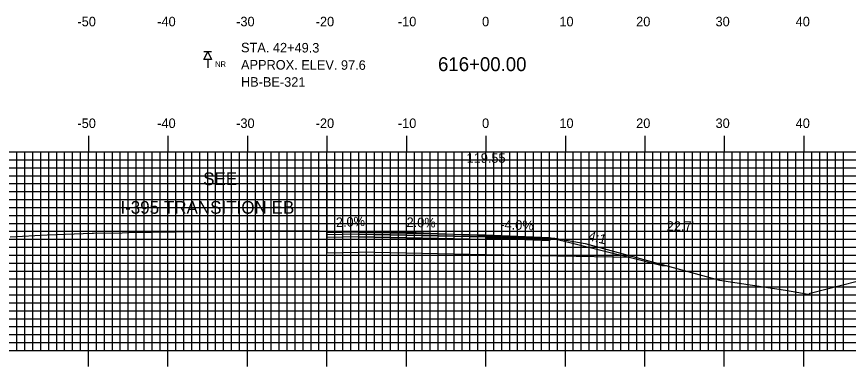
# Model space of a CAD drawing. Extents: x 844536 to 844879, y 363538 to 363758.
# Drawn here: x 844642.9 to 844747.6, y 363643.7 to 363687.7 of the extents above; entities that cross this region are included whole.
import ezdxf

# ---------------------------------------------------------------- set-up
doc = ezdxf.new("R2010")
doc.units = 0
for name, color, linetype in [('ANNOTATION', 7, 'Continuous'), ('BORING - NO REFUSAL', 7, 'Continuous'), ('D_Roadway_Centerline_Text', 7, 'Continuous'), ('D_Roadway_Edge_Shoulder', 7, 'Continuous'), ('D_Roadway_Edge_TW', 7, 'Continuous'), ('D_Roadway_FinishedGrade', 7, 'Continuous'), ('D_Roadway_Pavement', 7, 'Continuous'), ('D_Roadway_SlopeLines', 7, 'Continuous'), ('D_Roadway_SubGrade', 7, 'Continuous'), ('D_Text_Standard', 7, 'Continuous'), ('H_V ANNOTATION', 7, 'Continuous'), ('M_Roadway_Centerline', 7, 'Continuous'), ('MAJOR', 7, 'Continuous'), ('MINOR', 7, 'Continuous'), ('S_Roadway_Centerline', 7, 'Continuous')]:
    doc.layers.add(name, color=color, linetype=linetype)

msp = doc.modelspace()

# ---------------------------------------------------------------- linework, layer by layer
at = {"layer": 'BORING - NO REFUSAL'}
for p, q in [((844667.44, 363683.32), (844666.48, 363683.32)), ((844666.96, 363682.36), (844666.96, 363681.3))]:
    msp.add_line(p, q, dxfattribs=at)
msp.add_lwpolyline([(844666.96, 363683.32), (844667.44, 363682.36), (844666.48, 363682.36)], close=True, dxfattribs=at)
at = {"layer": 'D_Roadway_Edge_Shoulder'}
msp.add_lwpolyline([(844701.96, 363660.27), (844709.96, 363659.95), (844709.96, 363659.7), (844701.96, 363660.02)], close=True, dxfattribs=at)
at = {"layer": 'D_Roadway_Edge_TW'}
msp.add_lwpolyline([(844685.96, 363660.59), (844701.96, 363660.27), (844701.96, 363660.02), (844685.96, 363660.34)], close=True, dxfattribs=at)
at = {"layer": 'D_Roadway_FinishedGrade'}
for p, q in [((844685.96, 363660.59), (844681.96, 363660.51)), ((844685.96, 363660.34), (844681.96, 363660.26)), ((844685.96, 363660.01), (844681.96, 363659.93))]:
    msp.add_line(p, q, dxfattribs=at)
msp.add_lwpolyline([(844720.14, 363657.41), (844724.14, 363656.41), (844724.69, 363656.4)], dxfattribs=at)
at = {"layer": 'D_Roadway_Pavement'}
for points in [[(844685.96, 363660.34), (844701.96, 363660.02), (844701.96, 363659.69), (844685.96, 363660.01)], [(844701.96, 363660.02), (844709.96, 363659.7), (844709.96, 363659.53), (844701.96, 363659.85)]]:
    msp.add_lwpolyline(points, close=True, dxfattribs=at)
msp.add_lwpolyline([(844701.96, 363660.02), (844701.96, 363659.69)], dxfattribs=at)
msp.add_lwpolyline([(844701.96, 363660.02), (844701.96, 363659.69)], dxfattribs=at)
at = {"layer": 'D_Roadway_SlopeLines'}
msp.add_lwpolyline([(844709.96, 363659.95), (844710.39, 363659.84)], dxfattribs=at)
at = {"layer": 'D_Roadway_SubGrade'}
msp.add_line((844681.96, 363669.11), (844681.96, 363658.01), dxfattribs=at)
msp.add_lwpolyline([(844681.96, 363659.93), (844681.96, 363660.18), (844681.96, 363660.43), (844681.96, 363658.01), (844685.96, 363658.09), (844685.96, 363660.01)], dxfattribs=at)
for points in [[(844685.96, 363660.01), (844701.96, 363659.69), (844701.96, 363657.77), (844685.96, 363658.09)], [(844701.96, 363659.69), (844701.96, 363660.02), (844709.96, 363659.7), (844709.96, 363659.95), (844720.14, 363657.41), (844701.96, 363657.77)]]:
    msp.add_lwpolyline(points, close=True, dxfattribs=at)
at = {"layer": 'MAJOR'}
for p, q in [((844651.96, 363672.73), (844651.96, 363670.72)), ((844661.96, 363672.73), (844661.96, 363670.72)), ((844671.96, 363672.73), (844671.96, 363670.72)), ((844681.96, 363672.73), (844681.96, 363670.72)), ((844691.96, 363672.73), (844691.96, 363670.72)), ((844701.96, 363672.73), (844701.96, 363670.72)), ((844711.96, 363672.73), (844711.96, 363670.72)), ((844721.96, 363672.73), (844721.96, 363670.72)), ((844731.96, 363672.73), (844731.96, 363670.72)), ((844741.96, 363672.73), (844741.96, 363670.72)), ((844561.96, 363670.72), (844841.96, 363670.72)), ((844561.96, 363670.72), (844841.96, 363670.72)), ((844651.96, 363645.72), (844651.96, 363670.72)), ((844661.96, 363645.72), (844661.96, 363670.72)), ((844671.96, 363645.72), (844671.96, 363670.72)), ((844681.96, 363645.72), (844681.96, 363670.72)), ((844691.96, 363645.72), (844691.96, 363670.72)), ((844701.96, 363645.72), (844701.96, 363670.72)), ((844711.96, 363645.72), (844711.96, 363670.72)), ((844721.96, 363645.72), (844721.96, 363670.72)), ((844731.96, 363645.72), (844731.96, 363670.72)), ((844741.96, 363645.72), (844741.96, 363670.72)), ((844561.96, 363665.72), (844841.96, 363665.72)), ((844561.96, 363660.72), (844841.96, 363660.72)), ((844561.96, 363655.72), (844841.96, 363655.72)), ((844561.96, 363650.72), (844841.96, 363650.72)), ((844561.96, 363645.72), (844841.96, 363645.72)), ((844561.96, 363645.72), (844841.96, 363645.72)), ((844651.96, 363643.72), (844651.96, 363645.72)), ((844661.96, 363643.72), (844661.96, 363645.72)), ((844671.96, 363643.72), (844671.96, 363645.72)), ((844681.96, 363643.72), (844681.96, 363645.72)), ((844691.96, 363643.72), (844691.96, 363645.72)), ((844701.96, 363643.72), (844701.96, 363645.72)), ((844711.96, 363643.72), (844711.96, 363645.72)), ((844721.96, 363643.72), (844721.96, 363645.72)), ((844731.96, 363643.72), (844731.96, 363645.72)), ((844741.96, 363643.72), (844741.96, 363645.72))]:
    msp.add_line(p, q, dxfattribs=at)
at = {"layer": 'MINOR'}
for p, q in [((844642.96, 363645.72), (844642.96, 363670.72)), ((844643.96, 363645.72), (844643.96, 363670.72)), ((844644.96, 363645.72), (844644.96, 363670.72)), ((844645.96, 363645.72), (844645.96, 363670.72)), ((844646.96, 363645.72), (844646.96, 363670.72)), ((844647.96, 363645.72), (844647.96, 363670.72)), ((844648.96, 363645.72), (844648.96, 363670.72)), ((844649.96, 363645.72), (844649.96, 363670.72)), ((844650.96, 363645.72), (844650.96, 363670.72)), ((844652.96, 363645.72), (844652.96, 363670.72)), ((844653.96, 363645.72), (844653.96, 363670.72)), ((844654.96, 363645.72), (844654.96, 363670.72)), ((844655.96, 363645.72), (844655.96, 363670.72)), ((844656.96, 363645.72), (844656.96, 363670.72)), ((844657.96, 363645.72), (844657.96, 363670.72)), ((844658.96, 363645.72), (844658.96, 363670.72)), ((844659.96, 363645.72), (844659.96, 363670.72)), ((844660.96, 363645.72), (844660.96, 363670.72)), ((844662.96, 363645.72), (844662.96, 363670.72)), ((844663.96, 363645.72), (844663.96, 363670.72)), ((844664.96, 363645.72), (844664.96, 363670.72)), ((844665.96, 363645.72), (844665.96, 363670.72)), ((844666.96, 363645.72), (844666.96, 363670.72)), ((844667.96, 363645.72), (844667.96, 363670.72)), ((844668.96, 363645.72), (844668.96, 363670.72)), ((844669.96, 363645.72), (844669.96, 363670.72)), ((844670.96, 363645.72), (844670.96, 363670.72)), ((844672.96, 363645.72), (844672.96, 363670.72)), ((844673.96, 363645.72), (844673.96, 363670.72)), ((844674.96, 363645.72), (844674.96, 363670.72)), ((844675.96, 363645.72), (844675.96, 363670.72)), ((844676.96, 363645.72), (844676.96, 363670.72)), ((844677.96, 363645.72), (844677.96, 363670.72)), ((844678.96, 363645.72), (844678.96, 363670.72)), ((844679.96, 363645.72), (844679.96, 363670.72)), ((844680.96, 363645.72), (844680.96, 363670.72)), ((844682.96, 363645.72), (844682.96, 363670.72)), ((844683.96, 363645.72), (844683.96, 363670.72)), ((844684.96, 363645.72), (844684.96, 363670.72)), ((844685.96, 363645.72), (844685.96, 363670.72)), ((844686.96, 363645.72), (844686.96, 363670.72)), ((844687.96, 363645.72), (844687.96, 363670.72)), ((844688.96, 363645.72), (844688.96, 363670.72)), ((844689.96, 363645.72), (844689.96, 363670.72)), ((844690.96, 363645.72), (844690.96, 363670.72)), ((844692.96, 363645.72), (844692.96, 363670.72)), ((844693.96, 363645.72), (844693.96, 363670.72)), ((844694.96, 363645.72), (844694.96, 363670.72)), ((844695.96, 363645.72), (844695.96, 363670.72)), ((844696.96, 363645.72), (844696.96, 363670.72)), ((844697.96, 363645.72), (844697.96, 363670.72)), ((844698.96, 363645.72), (844698.96, 363670.72)), ((844699.96, 363645.72), (844699.96, 363670.72)), ((844700.96, 363645.72), (844700.96, 363670.72)), ((844702.96, 363645.72), (844702.96, 363670.72)), ((844703.96, 363645.72), (844703.96, 363670.72)), ((844704.96, 363645.72), (844704.96, 363670.72)), ((844705.96, 363645.72), (844705.96, 363670.72)), ((844706.96, 363645.72), (844706.96, 363670.72)), ((844707.96, 363645.72), (844707.96, 363670.72)), ((844708.96, 363645.72), (844708.96, 363670.72)), ((844709.96, 363645.72), (844709.96, 363670.72)), ((844710.96, 363645.72), (844710.96, 363670.72)), ((844712.96, 363645.72), (844712.96, 363670.72)), ((844713.96, 363645.72), (844713.96, 363670.72)), ((844714.96, 363645.72), (844714.96, 363670.72)), ((844715.96, 363645.72), (844715.96, 363670.72)), ((844716.96, 363645.72), (844716.96, 363670.72)), ((844717.96, 363645.72), (844717.96, 363670.72)), ((844718.96, 363645.72), (844718.96, 363670.72)), ((844719.96, 363645.72), (844719.96, 363670.72)), ((844720.96, 363645.72), (844720.96, 363670.72)), ((844722.96, 363645.72), (844722.96, 363670.72)), ((844723.96, 363645.72), (844723.96, 363670.72)), ((844724.96, 363645.72), (844724.96, 363670.72)), ((844725.96, 363645.72), (844725.96, 363670.72)), ((844726.96, 363645.72), (844726.96, 363670.72)), ((844727.96, 363645.72), (844727.96, 363670.72)), ((844728.96, 363645.72), (844728.96, 363670.72)), ((844729.96, 363645.72), (844729.96, 363670.72)), ((844730.96, 363645.72), (844730.96, 363670.72)), ((844732.96, 363645.72), (844732.96, 363670.72)), ((844733.96, 363645.72), (844733.96, 363670.72)), ((844734.96, 363645.72), (844734.96, 363670.72)), ((844735.96, 363645.72), (844735.96, 363670.72)), ((844736.96, 363645.72), (844736.96, 363670.72)), ((844737.96, 363645.72), (844737.96, 363670.72)), ((844738.96, 363645.72), (844738.96, 363670.72)), ((844739.96, 363645.72), (844739.96, 363670.72)), ((844740.96, 363645.72), (844740.96, 363670.72)), ((844742.96, 363645.72), (844742.96, 363670.72)), ((844743.96, 363645.72), (844743.96, 363670.72)), ((844744.96, 363645.72), (844744.96, 363670.72)), ((844745.96, 363645.72), (844745.96, 363670.72)), ((844746.96, 363645.72), (844746.96, 363670.72)), ((844561.96, 363669.72), (844841.96, 363669.72)), ((844561.96, 363668.72), (844841.96, 363668.72)), ((844561.96, 363667.72), (844841.96, 363667.72)), ((844561.96, 363666.72), (844841.96, 363666.72)), ((844561.96, 363664.72), (844841.96, 363664.72)), ((844561.96, 363663.72), (844841.96, 363663.72)), ((844561.96, 363662.72), (844841.96, 363662.72)), ((844561.96, 363661.72), (844841.96, 363661.72)), ((844561.96, 363659.72), (844841.96, 363659.72)), ((844561.96, 363658.72), (844841.96, 363658.72)), ((844561.96, 363657.72), (844841.96, 363657.72)), ((844561.96, 363656.72), (844841.96, 363656.72)), ((844561.96, 363654.72), (844841.96, 363654.72)), ((844561.96, 363653.72), (844841.96, 363653.72)), ((844561.96, 363652.72), (844841.96, 363652.72)), ((844561.96, 363651.72), (844841.96, 363651.72)), ((844561.96, 363649.72), (844841.96, 363649.72)), ((844561.96, 363648.72), (844841.96, 363648.72)), ((844561.96, 363647.72), (844841.96, 363647.72)), ((844561.96, 363646.72), (844841.96, 363646.72))]:
    msp.add_line(p, q, dxfattribs=at)
at = {"layer": 'S_Roadway_Centerline'}
msp.add_lwpolyline([(844642.11, 363660.04), (844646.78, 363660.26), (844652.41, 363660.47), (844652.6, 363660.47), (844656.19, 363660.54), (844657.03, 363660.55), (844668.83, 363660.75), (844674.74, 363660.8), (844680.93, 363660.79), (844692.44, 363660.58), (844693.06, 363660.57), (844693.19, 363660.56), (844694.1, 363660.52), (844694.13, 363660.52), (844694.86, 363660.49), (844696.88, 363660.4), (844708.97, 363659.9), (844710.64, 363659.84), (844714.46, 363659.17), (844728.29, 363655.42), (844731.35, 363654.58), (844739.64, 363653.3), (844742.53, 363652.82), (844742.66, 363652.82), (844742.77, 363652.92), (844748.68, 363654.43)], dxfattribs=at)

# ---------------------------------------------------------------- texts
at = {"layer": 'ANNOTATION'}
for s, p in [('SEE', (844666.38, 363666.53)), ('I-395 TRANSITION EB', (844655.97, 363662.93))]:
    msp.add_text(s, height=1.6, dxfattribs=at).set_placement(p)
for s, rotation, p in [('-2.0%', 2.2906, (844682.58, 363661.22)), ('2.0%', 358.8542, (844691.97, 363661.27)), ('-4.0%', 357.7094, (844703.76, 363661)), ('4:1', 345.9638, (844714.77, 363659.61))]:
    msp.add_text(s, height=1.2, rotation=rotation, dxfattribs=at).set_placement(p)
at = {"layer": 'BORING - NO REFUSAL'}
for s, p in [('STA. 42+49.3', (844671.15, 363683.25)), ('APPROX. ELEV. 97.6', (844671.15, 363681.09)), ('HB-BE-321', (844671.14, 363678.93))]:
    msp.add_text(s, height=1.2, rotation=359.8142, dxfattribs=at).set_placement(p)
msp.add_text('NR', height=0.7, dxfattribs=at).set_placement((844667.9, 363681.41))
at = {"layer": 'D_Roadway_Centerline_Text'}
msp.add_text('119.55', height=1.2, dxfattribs=at).set_placement((844699.53, 363669.34))
at = {"layer": 'D_Text_Standard'}
msp.add_text("22.7'", height=1.2, dxfattribs=at).set_placement((844724.72, 363660.78))
at = {"layer": 'H_V ANNOTATION'}
for s, height, p in [('-50', 1.2, (844650.57, 363686.52)), ('-40', 1.2, (844660.61, 363686.52)), ('-30', 1.2, (844670.54, 363686.52)), ('-20', 1.2, (844680.55, 363686.52)), ('-10', 1.2, (844690.89, 363686.52)), ('0', 1.2, (844701.48, 363686.52)), ('10', 1.2, (844711.21, 363686.52)), ('20', 1.2, (844720.87, 363686.52)), ('30', 1.2, (844730.86, 363686.52)), ('40', 1.2, (844740.94, 363686.52)), ('616+00.00', 1.75, (844695.94, 363680.88)), ('-50', 1.2, (844650.57, 363673.72)), ('-40', 1.2, (844660.61, 363673.72)), ('-30', 1.2, (844670.54, 363673.72)), ('-20', 1.2, (844680.55, 363673.72)), ('-10', 1.2, (844690.89, 363673.72)), ('0', 1.2, (844701.48, 363673.72)), ('10', 1.2, (844711.21, 363673.72)), ('20', 1.2, (844720.87, 363673.72)), ('30', 1.2, (844730.86, 363673.72)), ('40', 1.2, (844740.94, 363673.72))]:
    msp.add_text(s, height=height, dxfattribs=at).set_placement(p)
at = {"layer": 'M_Roadway_Centerline'}
for s, p in [('C', (844652.4, 363660.47)), ('L', (844652.41, 363660.47)), ('C', (844694.12, 363660.52)), ('L', (844694.13, 363660.51))]:
    msp.add_text(s, height=0.0146, dxfattribs=at).set_placement(p)

doc.saveas('drawing.dxf')
